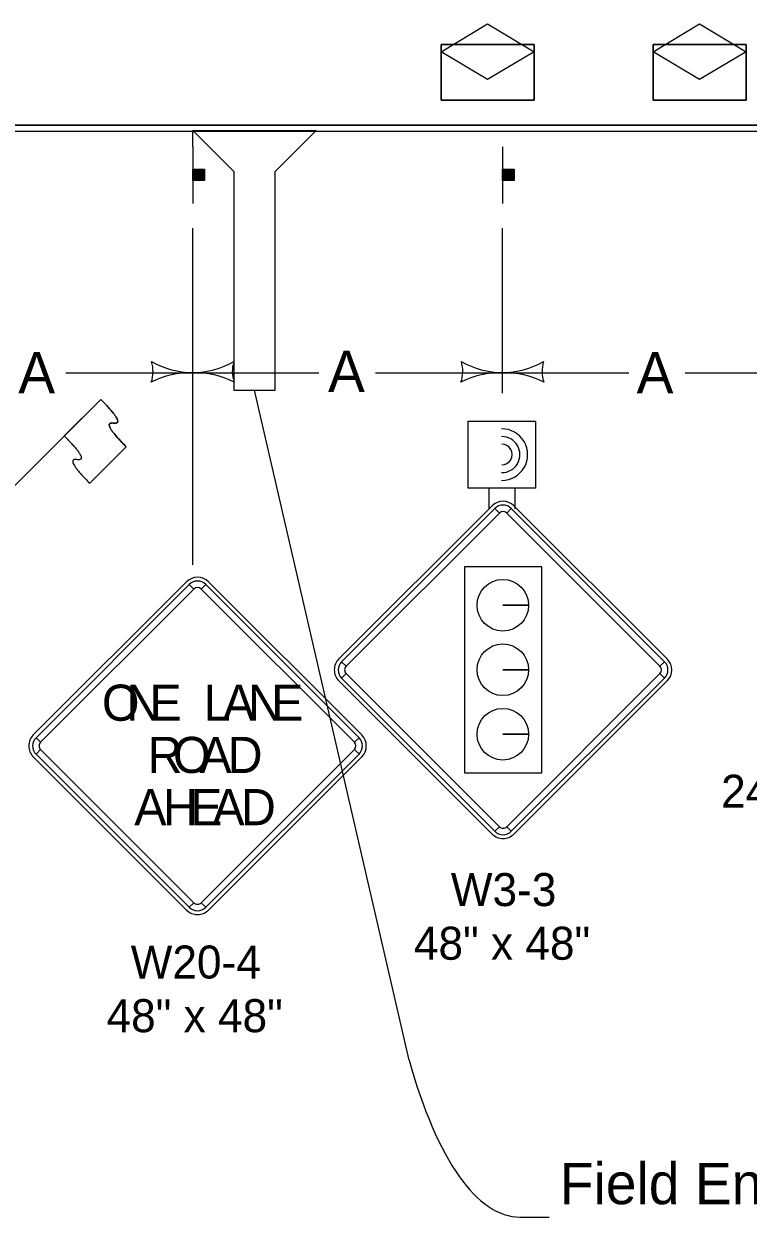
# Model space of a CAD drawing. Extents: x 10133 to 81668, y 4692 to 11018.
# Drawn here: x 21251 to 21602, y 6276 to 6854 of the extents above; entities that cross this region are included whole.
import ezdxf

# ---------------------------------------------------------------- set-up
doc = ezdxf.new("R2010")
doc.units = 0
for name, color, linetype in [('dsnCellElements', 7, 'Continuous'), ('dsnTextTabulation', 7, 'Continuous'), ('Level 5', 7, 'Continuous'), ('SheetAddendum', 7, 'Continuous'), ('SheetBorder', 7, 'Continuous'), ('ShtPlotIdentification', 7, 'Continuous')]:
    doc.layers.add(name, color=color, linetype=linetype)

msp = doc.modelspace()

# ---------------------------------------------------------------- linework, layer by layer
at = {"layer": 'dsnCellElements'}
for p, q in [((21452.85, 6816.84), (21452.85, 6843.84)), ((21452.85, 6843.84), (21497.85, 6843.84)), ((21452.85, 6816.84), (21452.85, 6843.84)), ((21452.85, 6843.84), (21497.85, 6843.84)), ((21497.85, 6843.84), (21452.85, 6843.84)), ((21452.85, 6843.84), (21452.85, 6816.84)), ((21497.85, 6816.84), (21497.85, 6843.84)), ((21497.85, 6843.84), (21497.85, 6816.84)), ((21497.85, 6816.84), (21497.85, 6843.84)), ((21555.53, 6816.84), (21555.53, 6843.84)), ((21555.53, 6843.84), (21600.53, 6843.84)), ((21555.53, 6816.84), (21555.53, 6843.84)), ((21555.53, 6843.84), (21600.53, 6843.84)), ((21600.53, 6843.84), (21555.53, 6843.84)), ((21555.53, 6843.84), (21555.53, 6816.84)), ((21600.53, 6816.84), (21600.53, 6843.84)), ((21600.53, 6843.84), (21600.53, 6816.84)), ((21600.53, 6816.84), (21600.53, 6843.84)), ((21452.85, 6816.84), (21497.85, 6816.84)), ((21497.85, 6816.84), (21452.85, 6816.84)), ((21452.85, 6816.84), (21497.85, 6816.84)), ((21555.53, 6816.84), (21600.53, 6816.84)), ((21600.53, 6816.84), (21555.53, 6816.84)), ((21555.53, 6816.84), (21600.53, 6816.84)), ((20982.53, 6804.8), (22482.53, 6804.8)), ((21332.53, 6794.3), (21332.53, 6766.8)), ((21482.53, 6794.3), (21482.53, 6766.8)), ((21332.94, 6777.86), (21332.94, 6783.44)), ((21333.22, 6783.44), (21333.22, 6777.86)), ((21333.48, 6777.86), (21333.48, 6783.44)), ((21333.75, 6783.44), (21333.75, 6777.86)), ((21333.97, 6777.86), (21333.97, 6783.44)), ((21334.18, 6783.44), (21334.18, 6777.86)), ((21334.52, 6777.86), (21334.52, 6783.44)), ((21334.78, 6783.44), (21334.78, 6777.86)), ((21335, 6777.86), (21334.98, 6783.44)), ((21335.32, 6783.44), (21335.32, 6777.86)), ((21335.7, 6777.86), (21335.7, 6783.44)), ((21336.13, 6783.44), (21336.13, 6777.86)), ((21336.35, 6777.86), (21336.33, 6783.44)), ((21336.77, 6783.44), (21336.78, 6777.86)), ((21336.99, 6777.86), (21336.99, 6783.44)), ((21337.31, 6783.44), (21337.31, 6777.86)), ((21337.53, 6777.86), (21337.53, 6783.44)), ((21337.85, 6783.44), (21337.85, 6777.86)), ((21482.94, 6777.86), (21482.94, 6783.44)), ((21483.22, 6783.44), (21483.22, 6777.86)), ((21483.48, 6777.86), (21483.48, 6783.44)), ((21483.75, 6783.44), (21483.75, 6777.86)), ((21483.97, 6777.86), (21483.97, 6783.44)), ((21484.18, 6783.44), (21484.18, 6777.86)), ((21484.52, 6777.86), (21484.52, 6783.44)), ((21484.78, 6783.44), (21484.78, 6777.86)), ((21485, 6777.86), (21484.98, 6783.44)), ((21485.32, 6783.44), (21485.32, 6777.86)), ((21485.7, 6777.86), (21485.7, 6783.44)), ((21486.13, 6783.44), (21486.13, 6777.86)), ((21486.35, 6777.86), (21486.33, 6783.44)), ((21486.77, 6783.44), (21486.78, 6777.86)), ((21486.99, 6777.86), (21486.99, 6783.44)), ((21487.31, 6783.44), (21487.31, 6777.86)), ((21487.53, 6777.86), (21487.53, 6783.44)), ((21487.85, 6783.44), (21487.85, 6777.86)), ((21332.53, 6591.63), (21332.53, 6754.8)), ((21482.53, 6674.8), (21482.53, 6754.8)), ((21271.03, 6684.8), (21332.53, 6684.8)), ((21332.53, 6684.8), (21393.7, 6684.8)), ((21421.03, 6684.8), (21482.53, 6684.8)), ((21482.53, 6684.8), (21543.7, 6684.8)), ((21571.03, 6684.8), (21632.53, 6684.8)), ((21437.41, 6351.62), (21362.46, 6676.35)), ((21475.99, 6628.86), (21475.99, 6618.86)), ((21488.49, 6628.86), (21488.49, 6618.86)), ((21491.03, 6275.56), (21505.25, 6275.56))]:
    msp.add_line(p, q, dxfattribs=at)
for points in [[(21332.62, 6777.86), (21332.62, 6783.48), (21338.25, 6783.48), (21338.25, 6777.86)], [(21482.62, 6777.86), (21482.62, 6783.48), (21488.25, 6783.48), (21488.25, 6777.86)], [(21465.99, 6628.86), (21465.99, 6661.36), (21498.49, 6661.36), (21498.49, 6628.86)]]:
    msp.add_lwpolyline(points, close=True, dxfattribs=at)
for centre, radius, start, end in [((21296.91, 6685.43), 16.42, 341.26665, 16.73335), ((21333.28, 6727.3), 42.5, 240.92751, 268.9824), ((21331.77, 6727.3), 42.5, 271.0176, 299.07249), ((21368.14, 6685.43), 16.42, 163.26665, 198.73335), ((21446.91, 6685.43), 16.42, 341.26665, 16.73335), ((21483.28, 6727.3), 42.5, 240.92751, 268.9824), ((21481.77, 6727.3), 42.5, 271.0176, 299.07249), ((21518.14, 6685.43), 16.42, 163.26665, 198.73335), ((21331.8, 6642.31), 42.5, 89.0176, 117.07249), ((21333.26, 6642.31), 42.5, 62.92751, 90.9824), ((21481.8, 6642.31), 42.5, 89.0176, 117.07249), ((21483.26, 6642.31), 42.5, 62.92751, 90.9824), ((21482.25, 6645.1), 12.5, 269.40414, 90.54446), ((21482.25, 6645.1), 12.5, 269.40414, 90.54446), ((21482.25, 6645.1), 8.75, 269.40414, 90.54446), ((21482.25, 6645.1), 5, 269.40414, 90.54446)]:
    msp.add_arc(centre, radius, start, end, dxfattribs=at)
msp.add_ellipse((21491.03, 6488.49), major_axis=(0, -212.93), ratio=0.328743, start_param=5.410521, end_param=6.283185, dxfattribs=at)
at = {"layer": 'dsnTextTabulation'}
for p, q in [((20982.53, 6804.8), (22482.53, 6804.8)), ((20982.53, 6804.8), (22482.53, 6804.8)), ((21627.53, 6804.8), (20982.53, 6804.8)), ((20982.53, 6801.8), (22482.53, 6801.8)), ((20982.53, 6801.8), (22482.53, 6801.8))]:
    msp.add_line(p, q, dxfattribs=at)
at = {"layer": 'Level 5'}
msp.add_line((21300.36, 6648.87), (21282.68, 6631.19), dxfattribs=at)
for points in [[(21287.98, 6671.86), (21300.36, 6659.47), (21287.98, 6661.24), (21300.36, 6648.87)], [(21270.3, 6654.17), (21282.68, 6641.79), (21270.31, 6643.56), (21282.68, 6631.19)]]:
    msp.add_open_spline(points, degree=2, dxfattribs=at)
at = {"layer": 'SheetAddendum'}
for p, q in [((21230.66, 6614.54), (21287.98, 6671.86)), ((21287.98, 6671.86), (21270.3, 6654.17)), ((21282.68, 6631.19), (21300.36, 6648.87)), ((21477.53, 6620.31), (21403.28, 6546.07)), ((21478.86, 6618.98), (21481.07, 6616.78)), ((21484.6, 6616.78), (21486.81, 6618.98)), ((21562.38, 6546.07), (21488.14, 6620.31)), ((21329.57, 6583.48), (21255.32, 6509.24)), ((21330.89, 6582.16), (21333.1, 6579.95)), ((21336.64, 6579.95), (21338.85, 6582.16)), ((21414.42, 6509.24), (21340.17, 6583.48)), ((21495.24, 6572.09), (21482.74, 6572.09)), ((21482.74, 6572.09), (21495.24, 6572.09)), ((21406.82, 6542.53), (21404.61, 6544.74)), ((21495.24, 6540.84), (21482.74, 6540.84)), ((21482.74, 6540.84), (21495.24, 6540.84)), ((21561.06, 6544.74), (21558.85, 6542.53)), ((21403.28, 6535.46), (21477.53, 6461.21)), ((21404.61, 6536.78), (21406.82, 6538.99)), ((21488.14, 6461.21), (21562.38, 6535.46)), ((21558.85, 6538.99), (21561.06, 6536.78)), ((21258.85, 6505.7), (21256.65, 6507.91)), ((21413.09, 6507.91), (21410.88, 6505.7)), ((21495.24, 6509.59), (21482.74, 6509.59)), ((21482.74, 6509.59), (21495.24, 6509.59)), ((21256.65, 6499.96), (21258.85, 6502.17)), ((21410.88, 6502.17), (21413.09, 6499.96)), ((21255.32, 6498.63), (21329.57, 6424.39)), ((21340.17, 6424.39), (21414.42, 6498.63)), ((21481.07, 6464.75), (21478.86, 6462.54)), ((21486.81, 6462.54), (21484.6, 6464.75)), ((21333.1, 6427.92), (21330.89, 6425.71)), ((21338.85, 6425.71), (21336.64, 6427.92))]:
    msp.add_line(p, q, dxfattribs=at)
for points in [[(21478.86, 6618.98), (21404.61, 6544.74), (21406.82, 6542.53), (21481.07, 6616.78), (21478.86, 6618.98)], [(21561.06, 6544.74), (21486.81, 6618.98), (21484.6, 6616.78), (21558.85, 6542.53), (21561.06, 6544.74)], [(21501.56, 6590.71), (21464.1, 6590.71), (21464.1, 6490.82), (21501.56, 6490.82), (21501.56, 6590.71)], [(21330.89, 6582.16), (21256.65, 6507.91), (21258.85, 6505.7), (21333.1, 6579.95), (21330.89, 6582.16)], [(21413.09, 6507.91), (21338.85, 6582.16), (21336.64, 6579.95), (21410.88, 6505.7), (21413.09, 6507.91)], [(21404.61, 6536.78), (21478.86, 6462.54), (21481.07, 6464.75), (21406.82, 6538.99), (21404.61, 6536.78)], [(21486.81, 6462.54), (21561.06, 6536.78), (21558.85, 6538.99), (21484.6, 6464.75), (21486.81, 6462.54)], [(21256.65, 6499.96), (21330.89, 6425.71), (21333.1, 6427.92), (21258.85, 6502.17), (21256.65, 6499.96)], [(21338.85, 6425.71), (21413.09, 6499.96), (21410.88, 6502.17), (21336.64, 6427.92), (21338.85, 6425.71)]]:
    msp.add_lwpolyline(points, close=True, dxfattribs=at)
for centre in [(21482.74, 6572.09), (21482.74, 6540.84), (21482.74, 6509.59)]:
    msp.add_circle(centre, 12.5, dxfattribs=at)
for centre, radius, start, end in [((21482.83, 6615.01), 7.5, 44.99999, 134.99974), ((21482.83, 6615.01), 5.62, 44.99999, 134.99974), ((21482.83, 6615.01), 2.5, 44.99999, 134.99974), ((21334.87, 6578.18), 7.5, 44.99999, 134.99974), ((21334.87, 6578.18), 5.62, 44.99999, 134.99974), ((21334.87, 6578.18), 2.5, 44.99999, 134.99974), ((21408.59, 6540.76), 7.5, 134.99974, 224.99995), ((21408.59, 6540.76), 5.62, 134.99974, 224.99995), ((21408.59, 6540.76), 2.5, 134.99974, 224.99995), ((21557.08, 6540.76), 2.5, 315.00016, 44.9998), ((21557.08, 6540.76), 5.62, 315.00016, 44.9998), ((21557.08, 6540.76), 7.5, 315.00016, 44.9998), ((21260.62, 6503.93), 7.5, 134.99974, 224.99995), ((21260.62, 6503.93), 5.62, 134.99974, 224.99995), ((21260.62, 6503.93), 2.5, 134.99974, 224.99995), ((21409.11, 6503.93), 2.5, 315.00016, 44.9998), ((21409.11, 6503.93), 5.62, 315.00016, 44.9998), ((21409.11, 6503.93), 7.5, 315.00016, 44.9998), ((21482.83, 6466.52), 7.5, 224.99995, 315.00016), ((21482.83, 6466.52), 5.62, 224.99995, 315.00016), ((21482.83, 6466.52), 2.5, 224.99995, 315.00016), ((21334.87, 6429.69), 5.62, 224.99995, 315.00016), ((21334.87, 6429.69), 2.5, 224.99995, 315.00016), ((21334.87, 6429.69), 7.5, 224.99995, 315.00016)]:
    msp.add_arc(centre, radius, start, end, dxfattribs=at)
for points in [[(21300.36, 6648.87), (21287.98, 6661.24), (21300.36, 6659.47), (21287.98, 6671.86)], [(21270.3, 6654.17), (21282.68, 6641.79), (21270.31, 6643.56), (21282.68, 6631.19)]]:
    msp.add_open_spline(points, degree=2, dxfattribs=at)
at = {"layer": 'SheetBorder'}
for p, q in [((21332.53, 6794.3), (21332.53, 6802.16)), ((21332.53, 6802.16), (21352.46, 6782.22)), ((21392.4, 6802.16), (21332.53, 6802.04)), ((21372.46, 6782.22), (21392.4, 6802.16)), ((21352.46, 6782.22), (21352.46, 6676.35)), ((21372.46, 6676.35), (21372.46, 6782.22)), ((21352.46, 6676.35), (21372.46, 6676.35))]:
    msp.add_line(p, q, dxfattribs=at)
at = {"layer": 'ShtPlotIdentification'}
for points in [[(21452.85, 6840.34), (21475.35, 6853.84), (21497.85, 6840.34), (21475.35, 6826.84)], [(21555.52, 6840.34), (21578.02, 6853.84), (21600.52, 6840.34), (21578.02, 6826.84)]]:
    msp.add_lwpolyline(points, close=True, dxfattribs=at)

# ---------------------------------------------------------------- texts
at = {"layer": 'dsnCellElements'}
for p in [(21248.06, 6674.77), (21398.06, 6675.39), (21547.52, 6674.78)]:
    msp.add_text('A', height=20, dxfattribs=at).set_placement(p)
at = {"layer": 'SheetAddendum'}
for s, height, p in [('O', 17.5, (21288.58, 6516.12)), ('N', 17.5, (21300.36, 6516.12)), ('E', 17.5, (21311.59, 6516.12)), ('L', 17.5, (21337.84, 6516.12)), ('A', 17.5, (21347.03, 6516.12)), ('N', 17.5, (21359.3, 6516.12)), ('E', 17.5, (21370.53, 6516.12)), ('R', 17.5, (21310.69, 6490.81)), ('O', 17.5, (21322.98, 6490.81)), ('A', 17.5, (21335.82, 6490.81)), ('D', 17.5, (21349.47, 6490.81)), ('24" x 36"', 16, (21588.46, 6473.97)), ('A', 17.5, (21304.25, 6465.5)), ('H', 17.5, (21318.12, 6465.5)), ('E', 17.5, (21331.34, 6465.5)), ('A', 17.5, (21342.05, 6465.5)), ('D', 17.5, (21355.91, 6465.5)), ('W3-3', 16, (21457.54, 6426.3)), ('48" x 48"', 16, (21439.66, 6400.3)), ('W20-4', 16, (21302.5, 6391.19)), ('48" x 48"', 16, (21290.8, 6365.19))]:
    msp.add_text(s, height=height, dxfattribs=at).set_placement(p)
at = {"layer": 'SheetBorder'}
msp.add_text('Field Ent.', height=20, dxfattribs=at).set_placement((21510.33, 6281.84))

doc.saveas('drawing.dxf')
